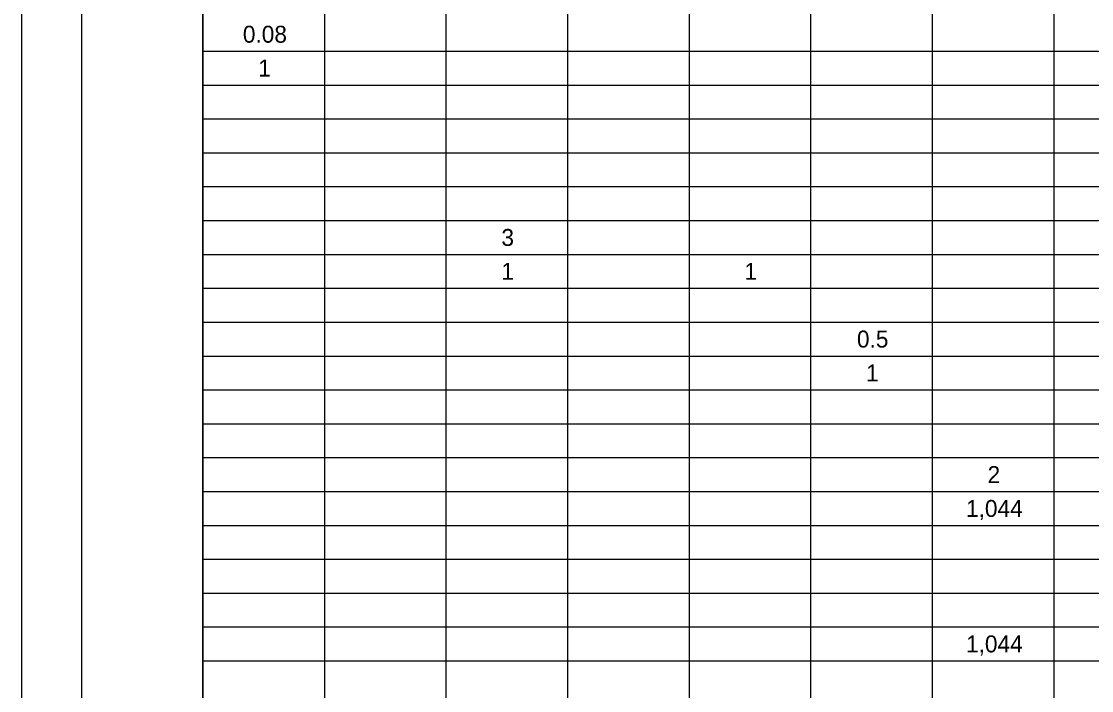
# Model space of a CAD drawing. Extents: x 0 to 34, y 0 to 22.
# Drawn here: x 0 to 8.85, y 10.89 to 16.43 of the extents above; entities that cross this region are included whole.
import ezdxf

# ---------------------------------------------------------------- set-up
doc = ezdxf.new("R2010")
doc.units = 0
for name, color, linetype in [('SH_Border', 7, 'Continuous'), ('SH_Cut_Line', 7, 'Continuous'), ('SH_Data', 7, 'Continuous'), ('SH_Text', 7, 'Continuous')]:
    doc.layers.add(name, color=color, linetype=linetype)

msp = doc.modelspace()

# ---------------------------------------------------------------- linework, layer by layer
at = {"layer": 'SH_Border'}
for points in [[(0.5, 21.5), (1.5, 21.5), (1.5, 0.5), (0.5, 0.5)], [(1.5, 21.5), (33.5, 21.5), (33.5, 0.5), (1.5, 0.5)]]:
    msp.add_lwpolyline(points, close=True, dxfattribs=at)
at = {"layer": 'SH_Cut_Line'}
msp.add_lwpolyline([(0, 0), (34, 0), (34, 22), (0, 22)], close=True, dxfattribs=at)
at = {"layer": 'SH_Data'}
for p, q in [((1.5, 21.5), (1.5, 0.5)), ((2.5047, 20.94), (2.5047, 0.5)), ((3.5094, 20.94), (3.5094, 0.5)), ((4.5141, 20.94), (4.5141, 0.5)), ((5.5188, 20.94), (5.5188, 0.5)), ((6.5235, 20.94), (6.5235, 0.5)), ((7.5282, 20.94), (7.5282, 0.5)), ((8.5329, 20.94), (8.5329, 0.5)), ((1.5, 16.18), (32.0036, 16.18)), ((1.5, 15.9), (32.0036, 15.9)), ((1.5, 15.62), (32.0036, 15.62)), ((1.5, 15.34), (32.0036, 15.34)), ((1.5, 15.06), (32.0036, 15.06)), ((1.5, 14.78), (32.0036, 14.78)), ((1.5, 14.5), (32.0036, 14.5)), ((1.5, 14.22), (32.0036, 14.22)), ((1.5, 13.94), (32.0036, 13.94)), ((1.5, 13.66), (32.0036, 13.66)), ((1.5, 13.38), (32.0036, 13.38)), ((1.5, 13.1), (32.0036, 13.1)), ((1.5, 12.82), (32.0036, 12.82)), ((1.5, 12.54), (32.0036, 12.54)), ((1.5, 12.26), (32.0036, 12.26)), ((1.5, 11.98), (32.0036, 11.98)), ((1.5, 11.7), (32.0036, 11.7)), ((1.5, 11.42), (32.0036, 11.42)), ((1.5, 11.14), (32.0036, 11.14))]:
    msp.add_line(p, q, dxfattribs=at)

# ---------------------------------------------------------------- texts
at = {"layer": 'SH_Text'}
for s, p in [('0.08', (1.8305, 16.25)), ('1', (1.9575, 15.97)), ('3', (3.9675, 14.57)), ('1', (3.9669, 14.29)), ('1', (5.9763, 14.29)), ('0.5', (6.906, 13.73)), ('1', (6.981, 13.45)), ('2', (7.9858, 12.61)), ('1,044', (7.8075, 12.33)), ('1,044', (7.8075, 11.21))]:
    msp.add_text(s, height=0.14, dxfattribs=at).set_placement(p)

doc.saveas('drawing.dxf')
